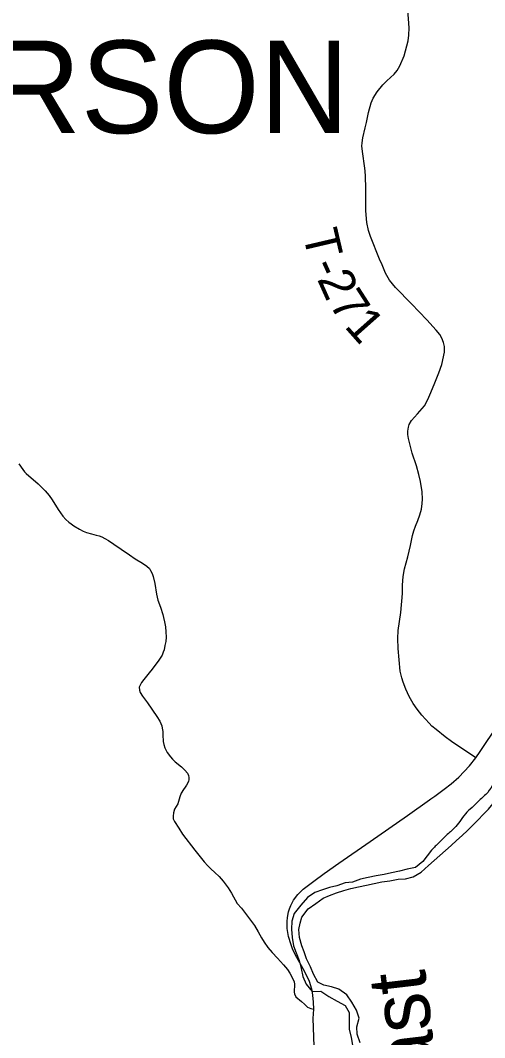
# Model space of a CAD drawing. Extents: x -10.5 to 40.6, y -3.2 to 22.
# Drawn here: x -7.857 to -7.105, y 17.758 to 19.405 of the extents above; entities that cross this region are included whole.
import ezdxf

# ---------------------------------------------------------------- set-up
doc = ezdxf.new("R2010")
doc.units = 0
for name, color, linetype in [('GM_X_Major_River', 7, 'Continuous'), ('GM_X_Major_River_Text', 7, 'Continuous'), ('GM_X_State_Route', 7, 'Continuous'), ('GM_X_Township_Road', 7, 'Continuous'), ('GM_X_Township_Road_Text', 7, 'Continuous'), ('GM_X_Township_Text', 7, 'Continuous')]:
    doc.layers.add(name, color=color, linetype=linetype)

msp = doc.modelspace()

# ---------------------------------------------------------------- linework, layer by layer
at = {"layer": 'GM_X_Major_River'}
for points in [[(-7.1906, 18.061), (-7.2045, 18.0429), (-7.2164, 18.0331), (-7.23, 18.0302), (-7.2425, 18.0273), (-7.2557, 18.0244), (-7.2674, 18.0219), (-7.2806, 18.0198), (-7.2931, 18.0169), (-7.3059, 18.014), (-7.3187, 18.0092), (-7.3308, 18.0082), (-7.344, 18.0034), (-7.3557, 18.0005), (-7.3674, 17.9969), (-7.3798, 17.9928), (-7.3918, 17.9846), (-7.4022, 17.9719), (-7.4133, 17.9588), (-7.4172, 17.9462), (-7.4177, 17.9333), (-7.4167, 17.9197), (-7.4141, 17.9061), (-7.4101, 17.8948), (-7.405, 17.8823), (-7.4017, 17.8695), (-7.3991, 17.8567), (-7.3936, 17.8443), (-7.3839, 17.8323), (-7.3702, 17.8326), (-7.3568, 17.8241), (-7.3438, 17.8168), (-7.3307, 17.8098), (-7.3241, 17.7982), (-7.3242, 17.7845), (-7.3243, 17.7716), (-7.3206, 17.758), (-7.3189, 17.7452)], [(-7.306, 17.7492), (-7.3109, 17.7632), (-7.3115, 17.7753), (-7.308, 17.7894), (-7.312, 17.8022), (-7.3195, 17.8153), (-7.328, 17.8269), (-7.3407, 17.8362), (-7.3529, 17.8401), (-7.3651, 17.8425), (-7.3747, 17.8476), (-7.3818, 17.8604), (-7.3869, 17.8721), (-7.3933, 17.8852), (-7.3969, 17.8965), (-7.4009, 17.9063), (-7.4046, 17.9199), (-7.4056, 17.9328), (-7.4035, 17.9431), (-7.4006, 17.9526), (-7.3903, 17.9661), (-7.3783, 17.975), (-7.366, 17.9832), (-7.3558, 17.988), (-7.3445, 17.992), (-7.3325, 17.996), (-7.3212, 17.9993), (-7.3087, 18.0018), (-7.2959, 18.0043), (-7.2713, 18.0097), (-7.2581, 18.0115), (-7.2449, 18.0144), (-7.2328, 18.015), (-7.2203, 18.0179), (-7.2076, 18.0257), (-7.1956, 18.0366)]]:
    msp.add_lwpolyline(points, dxfattribs=at)
for points in [[(-6.4692, 18.3291), (-6.4793, 18.324), (-6.4902, 18.3181), (-6.5038, 18.3122), (-6.514, 18.3074), (-6.5268, 18.3034), (-6.5396, 18.3005), (-6.5498, 18.2988), (-6.562, 18.3001), (-6.5746, 18.3033), (-6.5841, 18.3039), (-6.5951, 18.3041), (-6.6069, 18.3077), (-6.6183, 18.3098), (-6.6293, 18.3111), (-6.6423, 18.3147), (-6.6556, 18.319), (-6.6686, 18.3196), (-6.6807, 18.322), (-6.6903, 18.3256), (-6.7156, 18.3396), (-6.7256, 18.3505), (-6.733, 18.3636), (-6.7397, 18.3761), (-6.7468, 18.3888), (-6.7504, 18.4021), (-6.7586, 18.4148), (-6.7664, 18.4284), (-6.7704, 18.4405), (-6.7759, 18.4525), (-6.7811, 18.4657), (-6.787, 18.4785), (-6.7948, 18.4906), (-6.8053, 18.5037), (-6.8146, 18.5164), (-6.8266, 18.5291), (-6.8366, 18.5381), (-6.8471, 18.5508), (-6.8597, 18.5597), (-6.8724, 18.5663), (-6.8854, 18.571), (-6.8976, 18.5761), (-6.9117, 18.5804), (-6.9216, 18.5837), (-6.9353, 18.5831), (-6.9455, 18.5814), (-6.9591, 18.5777), (-6.9707, 18.568), (-6.9834, 18.5617), (-6.9955, 18.5554), (-7.0055, 18.5424), (-7.0091, 18.5328), (-7.0115, 18.5198), (-7.0113, 18.5073), (-7.01, 18.4944), (-7.0094, 18.4819), (-7.0088, 18.469), (-7.0082, 18.4565), (-7.0083, 18.4443), (-7.0081, 18.4299), (-7.0086, 18.417), (-7.0073, 18.4045), (-7.0051, 18.3908), (-7.0053, 18.3779), (-7.0058, 18.3657), (-7.0053, 18.3563), (-7.0066, 18.3437), (-7.0067, 18.3312), (-7.0092, 18.3178), (-7.0134, 18.2988), (-7.0158, 18.2854), (-7.022, 18.2713), (-7.0264, 18.2606), (-7.0341, 18.2475), (-7.0408, 18.2371), (-7.0463, 18.2268), (-7.0541, 18.2172), (-7.0637, 18.2048), (-7.0715, 18.1926), (-7.0781, 18.1822), (-7.0896, 18.1687), (-7.0996, 18.1548), (-7.1134, 18.1417), (-7.125, 18.1301), (-7.1358, 18.12), (-7.1447, 18.1074), (-7.1536, 18.0973), (-7.1667, 18.0849), (-7.1783, 18.0737), (-7.1906, 18.061)], [(-7.1956, 18.0366), (-7.0613, 18.1745), (-7.0524, 18.1879), (-7.0443, 18.2006), (-7.0366, 18.2144), (-7.0277, 18.2279), (-7.0207, 18.2386), (-7.0126, 18.2517), (-7.0016, 18.2731), (-6.9954, 18.2877), (-6.994, 18.2976), (-6.9905, 18.3109), (-6.9881, 18.3254), (-6.9878, 18.3357), (-6.9876, 18.3452), (-6.9889, 18.355), (-6.9884, 18.3668), (-6.9878, 18.3767), (-6.9899, 18.3903), (-6.9901, 18.4013), (-6.9895, 18.4108), (-6.9905, 18.4237), (-6.993, 18.437), (-6.994, 18.4476), (-6.9949, 18.4578), (-6.9966, 18.4684), (-6.998, 18.4813), (-6.9964, 18.4969), (-6.9951, 18.511), (-6.9938, 18.5228), (-6.9876, 18.537), (-6.9779, 18.5482), (-6.9663, 18.5556), (-6.9534, 18.5581), (-6.9405, 18.5598), (-6.9296, 18.5615), (-6.9182, 18.5629), (-6.9087, 18.5623), (-6.8966, 18.5613), (-6.8821, 18.5566), (-6.869, 18.5485), (-6.856, 18.5381), (-6.8455, 18.5277), (-6.8351, 18.5145), (-6.8246, 18.5011), (-6.8175, 18.489), (-6.8063, 18.4755), (-6.7985, 18.462), (-6.7907, 18.4496), (-6.7828, 18.4338), (-6.7758, 18.4225), (-6.7722, 18.4127), (-6.7717, 18.4021), (-6.7654, 18.3893), (-6.7579, 18.3773), (-6.7535, 18.364), (-6.7488, 18.3508), (-6.7425, 18.3384), (-6.7305, 18.3268), (-6.7183, 18.3206), (-6.7049, 18.3129), (-6.6953, 18.3088), (-6.67, 18.2964), (-6.6571, 18.2955), (-6.6469, 18.2941), (-6.6328, 18.2921), (-6.621, 18.2911), (-6.6089, 18.2925), (-6.5971, 18.2919), (-6.5876, 18.286), (-6.5746, 18.2817), (-6.562, 18.2793), (-6.5496, 18.2821), (-6.5366, 18.2805), (-6.5235, 18.2875), (-6.511, 18.2919), (-6.4975, 18.2971), (-6.4742, 18.3093), (-6.4611, 18.319), (-6.4471, 18.3249), (-6.4358, 18.3297)]]:
    msp.add_spline(points, degree=3, dxfattribs=at)
at = {"layer": 'GM_X_State_Route'}
for points in [[(-7.1915, 18.1443), (-7.1854, 18.1488), (-7.1702, 18.1599), (-7.1588, 18.1688), (-7.1465, 18.1793), (-7.1292, 18.1976), (-7.119, 18.2106), (-7.1116, 18.2209), (-7.0832, 18.2636)], [(-7.4009, 17.9959), (-7.3988, 17.9981), (-7.3815, 18.0111), (-7.3644, 18.0235), (-7.3406, 18.0401), (-7.2903, 18.0752), (-7.2295, 18.1175), (-7.1938, 18.1427), (-7.1915, 18.1443)], [(-7.381, 17.7436), (-7.3823, 17.7886), (-7.3815, 17.8035), (-7.3821, 17.8152), (-7.3829, 17.8262), (-7.3842, 17.834), (-7.3862, 17.8414), (-7.3885, 17.8484), (-7.3958, 17.8642), (-7.4114, 17.8921), (-7.4157, 17.9015), (-7.4182, 17.9078), (-7.4222, 17.9214), (-7.4235, 17.9278), (-7.4244, 17.9341), (-7.4248, 17.9405), (-7.4247, 17.9458), (-7.4241, 17.952), (-7.4224, 17.9615), (-7.421, 17.9661), (-7.4187, 17.9716), (-7.4143, 17.98), (-7.4074, 17.9895), (-7.4009, 17.9959)]]:
    msp.add_lwpolyline(points, dxfattribs=at)
at = {"layer": 'GM_X_Township_Road'}
for points in [[(-7.119, 18.2106), (-7.1585, 18.2373), (-7.1685, 18.2448), (-7.1831, 18.2564), (-7.1899, 18.2622), (-7.1946, 18.2668), (-7.2063, 18.2795), (-7.2137, 18.2893), (-7.2202, 18.2988), (-7.2267, 18.31), (-7.2324, 18.3218), (-7.2368, 18.3334), (-7.239, 18.3402), (-7.2412, 18.3512), (-7.2445, 18.3878), (-7.2454, 18.404), (-7.2449, 18.4166), (-7.2405, 18.4459), (-7.2377, 18.4767), (-7.2375, 18.4905), (-7.2368, 18.5044), (-7.2343, 18.5165), (-7.2288, 18.5362), (-7.2249, 18.5544), (-7.2214, 18.5708), (-7.2194, 18.578), (-7.2166, 18.5857), (-7.2129, 18.595), (-7.2095, 18.6043), (-7.2068, 18.6133), (-7.2058, 18.6225), (-7.2054, 18.6296), (-7.206, 18.6413), (-7.2086, 18.658), (-7.2111, 18.6692), (-7.2152, 18.6836), (-7.2222, 18.7042), (-7.2254, 18.7167), (-7.2278, 18.7277), (-7.2288, 18.7342), (-7.2289, 18.7395), (-7.2282, 18.7462), (-7.2268, 18.7505), (-7.2233, 18.7566), (-7.2131, 18.7676), (-7.2018, 18.7805), (-7.1965, 18.7907), (-7.1915, 18.8022), (-7.1852, 18.8181), (-7.1787, 18.8339), (-7.1741, 18.8477), (-7.1698, 18.8674), (-7.1695, 18.8768), (-7.1711, 18.8834), (-7.1738, 18.8902), (-7.1774, 18.8961), (-7.1833, 18.9029), (-7.1984, 18.9199), (-7.2229, 18.9457), (-7.2489, 18.9724), (-7.2585, 18.9842), (-7.2654, 18.9953), (-7.2707, 19.0089), (-7.2748, 19.018), (-7.2896, 19.0549), (-7.2928, 19.0643), (-7.2956, 19.0772), (-7.2969, 19.0961), (-7.297, 19.1153), (-7.297, 19.1331), (-7.2977, 19.1522), (-7.298, 19.1609), (-7.299, 19.1692), (-7.3021, 19.1886), (-7.3034, 19.2011), (-7.3029, 19.2065), (-7.3018, 19.2147), (-7.2979, 19.2306), (-7.2959, 19.2395), (-7.2927, 19.2558), (-7.2885, 19.2712), (-7.2853, 19.2789), (-7.2789, 19.2891), (-7.2697, 19.3001), (-7.2628, 19.3068), (-7.2512, 19.3178), (-7.2465, 19.3237), (-7.2418, 19.331), (-7.2348, 19.3472), (-7.2283, 19.3714), (-7.2272, 19.3807), (-7.2268, 19.3926), (-7.2296, 19.4286)], [(-7.8593, 18.6868), (-7.8529, 18.6777), (-7.8501, 18.6739), (-7.8472, 18.671), (-7.8281, 18.6542), (-7.8165, 18.6428), (-7.8102, 18.6353), (-7.8055, 18.6285), (-7.7954, 18.6128), (-7.7916, 18.6071), (-7.7878, 18.6019), (-7.7829, 18.5967), (-7.7781, 18.5923), (-7.7744, 18.5893), (-7.77, 18.5862), (-7.7611, 18.5808), (-7.7552, 18.5777), (-7.7497, 18.5756), (-7.7418, 18.5732), (-7.7342, 18.5713), (-7.7293, 18.5701), (-7.7248, 18.5685), (-7.7199, 18.566), (-7.7138, 18.5623), (-7.7053, 18.5564), (-7.6937, 18.5485), (-7.6801, 18.5392), (-7.6706, 18.5329), (-7.6589, 18.5257), (-7.6517, 18.5211), (-7.6477, 18.5171), (-7.6458, 18.514), (-7.6433, 18.5094), (-7.6415, 18.5045), (-7.6389, 18.4927), (-7.6364, 18.4754), (-7.6339, 18.4657), (-7.6297, 18.4544), (-7.6259, 18.4427), (-7.6247, 18.4377), (-7.6233, 18.4307), (-7.6219, 18.4226), (-7.6212, 18.4147), (-7.6208, 18.4062), (-7.6214, 18.3989), (-7.6226, 18.3927), (-7.6241, 18.3858), (-7.6253, 18.3817), (-7.6273, 18.377), (-7.6324, 18.3689), (-7.6432, 18.3544), (-7.6484, 18.3481), (-7.6566, 18.3374), (-7.6605, 18.3325), (-7.6627, 18.3284), (-7.6641, 18.3249), (-7.6639, 18.3204), (-7.6625, 18.3163), (-7.6587, 18.3106), (-7.6507, 18.2999), (-7.6356, 18.2777), (-7.631, 18.2702), (-7.6291, 18.2662), (-7.6278, 18.2626), (-7.6269, 18.2585), (-7.6261, 18.2534), (-7.6259, 18.2477), (-7.6255, 18.2371), (-7.6245, 18.232), (-7.6228, 18.2269), (-7.6191, 18.2194), (-7.6138, 18.2124), (-7.6102, 18.2085), (-7.6061, 18.2044), (-7.596, 18.1961), (-7.5904, 18.1907), (-7.5862, 18.1857), (-7.5845, 18.1822), (-7.5838, 18.1786), (-7.5838, 18.1756), (-7.5846, 18.1721), (-7.5876, 18.1665), (-7.5898, 18.163), (-7.5924, 18.1595), (-7.5964, 18.1537), (-7.5986, 18.1477), (-7.6018, 18.136), (-7.6071, 18.1273), (-7.6087, 18.1216), (-7.6095, 18.1164), (-7.6091, 18.1118), (-7.6073, 18.1076), (-7.6002, 18.0966), (-7.5939, 18.0873), (-7.5741, 18.0612), (-7.5591, 18.0425), (-7.5532, 18.0358), (-7.5481, 18.0307), (-7.5415, 18.0248), (-7.5346, 18.0184), (-7.5282, 18.0112), (-7.5248, 18.0069), (-7.5199, 18.0002), (-7.5147, 17.9917), (-7.5054, 17.9749), (-7.4988, 17.967), (-7.4773, 17.9393), (-7.4713, 17.9292), (-7.466, 17.919), (-7.462, 17.9122), (-7.4559, 17.9038), (-7.449, 17.8957), (-7.4401, 17.8862), (-7.4303, 17.8756), (-7.4238, 17.8678), (-7.4204, 17.8622), (-7.4157, 17.8538), (-7.4132, 17.848), (-7.4124, 17.8441), (-7.4133, 17.8314), (-7.4125, 17.8284), (-7.4103, 17.8238), (-7.4012, 17.816), (-7.3967, 17.8117), (-7.3916, 17.8072), (-7.3861, 17.8047), (-7.3815, 17.8035)]]:
    msp.add_lwpolyline(points, dxfattribs=at)

# ---------------------------------------------------------------- texts
at = {"layer": 'GM_X_Major_River_Text'}
msp.add_text('East', height=0.09469, rotation=96.7272, dxfattribs=at).set_placement((-7.1717, 17.6177))
at = {"layer": 'GM_X_Township_Road_Text'}
for s, rotation, p in [('T', 283.1745, (-7.3997, 19.0599)), ('-', 294.2147, (-7.3862, 19.0072)), ('2', 294.1976, (-7.3766, 18.986)), ('7', 302.6961, (-7.3579, 18.946)), ('1', 311.5795, (-7.3332, 18.9089))]:
    msp.add_text(s, height=0.0568, rotation=rotation, dxfattribs=at).set_placement(p)
at = {"layer": 'GM_X_Township_Text'}
msp.add_text('JEFFERSON', height=0.15, rotation=0, dxfattribs=at).set_placement((-8.5166, 19.2221))

doc.saveas('drawing.dxf')
